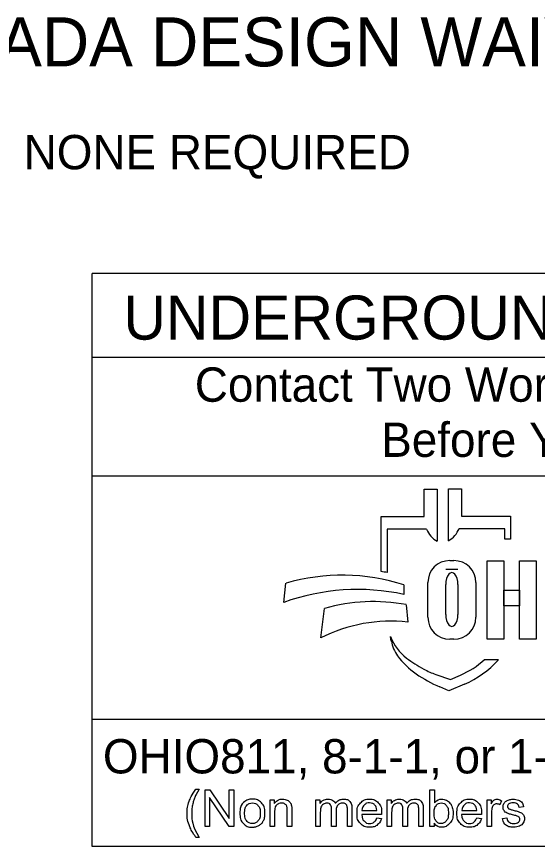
# Model space of a CAD drawing. Extents: x 0 to 34, y 0 to 22.
# Drawn here: x 2.07 to 4.196, y 2.143 to 5.529 of the extents above; entities that cross this region are included whole.
import ezdxf

# ---------------------------------------------------------------- set-up
doc = ezdxf.new("R2010")
doc.units = 0
doc.layers.add('SH_Data', color=7, linetype='Continuous')
doc.layers.add('SH_Text', color=7, linetype='Continuous')

msp = doc.modelspace()

# ---------------------------------------------------------------- linework, layer by layer
at = {"layer": 'SH_Data'}
for p, q in [((2.3775, 2.1428), (2.3775, 4.4803)), ((6.6275, 4.4803), (2.3775, 4.4803)), ((2.3775, 4.1387), (6.6275, 4.1387)), ((2.3775, 3.6553), (6.6275, 3.6553)), ((6.6275, 2.6607), (2.3775, 2.6607)), ((6.6275, 2.1428), (2.3775, 2.1428))]:
    msp.add_line(p, q, dxfattribs=at)
at = {"layer": 'SH_Text'}
for p, q in [((3.7335, 3.4883), (3.7335, 3.5998)), ((3.7335, 3.5998), (3.7872, 3.5998)), ((3.7872, 3.5998), (3.7872, 3.3877)), ((3.8329, 3.39), (3.8329, 3.6021)), ((3.8329, 3.6021), (3.8865, 3.6021)), ((3.8865, 3.6021), (3.8865, 3.4906)), ((3.5576, 3.2644), (3.5576, 3.4883)), ((3.5576, 3.4883), (3.7335, 3.4883)), ((3.8865, 3.4906), (4.0857, 3.4906)), ((4.0857, 3.4906), (4.0857, 3.3968)), ((3.5828, 3.4369), (3.5828, 3.26)), ((3.7439, 3.4369), (3.5828, 3.4369)), ((4.0625, 3.4392), (3.8761, 3.4392)), ((4.0625, 3.3968), (4.0625, 3.4392)), ((4.0857, 3.3968), (4.0625, 3.3968)), ((3.8385, 3.3091), (3.8551, 3.3091)), ((3.8718, 3.2721), (3.822, 3.2721)), ((3.7491, 3.0776), (3.7491, 3.2196)), ((3.9445, 3.2196), (3.9445, 3.0776)), ((3.1602, 3.1381), (3.1696, 3.2162)), ((3.6509, 3.2097), (3.6509, 3.1709)), ((3.822, 3.089), (3.822, 3.2114)), ((3.8718, 3.2114), (3.8718, 3.089)), ((3.6608, 3.1291), (3.6671, 3.0582)), ((3.312, 2.9936), (3.3267, 3.1137)), ((3.5997, 2.9807), (3.5967, 2.9986)), ((3.8551, 2.9882), (3.8385, 2.9882)), ((3.98, 2.9048), (4.0375, 2.9048)), ((3.7816, 2.8444), (3.841, 2.8239)), ((3.841, 2.8239), (3.8821, 2.8417)), ((3.835, 2.7769), (3.7976, 2.7934)), ((3.8983, 2.8044), (3.835, 2.7769))]:
    msp.add_line(p, q, dxfattribs=at)
for points in [[(3.991, 3.3081), (4.0589, 3.3081), (4.0589, 2.9881), (3.991, 2.9881)], [(4.1231, 3.3081), (4.1911, 3.3081), (4.1911, 2.9881), (4.1231, 2.9881)], [(4.0589, 3.1882), (4.1231, 3.1882), (4.1231, 3.1242), (4.0589, 3.1242)]]:
    msp.add_lwpolyline(points, close=True, dxfattribs=at)
for points in [[(2.8021, 2.3766), (2.8153, 2.3766)], [(2.8389, 2.2239), (2.8389, 2.3741), (2.8592, 2.3741), (2.9382, 2.2561), (2.9382, 2.3741), (2.9572, 2.3741), (2.9572, 2.2239), (2.9369, 2.2239), (2.8579, 2.3419), (2.8579, 2.2239), (2.8389, 2.2239)], [(3.7743, 2.2239), (3.7573, 2.2239), (3.7573, 2.3741), (3.7757, 2.3741), (3.7757, 2.3206)], [(3.1048, 2.2239), (3.1048, 2.3328), (3.1214, 2.3328), (3.1214, 2.3173)], [(3.2912, 2.2239), (3.2912, 2.3328), (3.3077, 2.3328), (3.3077, 2.3174)], [(3.5826, 2.2239), (3.5826, 2.3328), (3.5991, 2.3328), (3.5991, 2.3174)], [(3.9904, 2.2239), (3.9904, 2.3328), (4.007, 2.3328), (4.007, 2.3163)], [(4.0495, 2.3293), (4.043, 2.3122)], [(4.1394, 2.3046), (4.1213, 2.3022)], [(3.1233, 2.2833), (3.1233, 2.2239), (3.1048, 2.2239)], [(3.1932, 2.2908), (3.1932, 2.2239), (3.1748, 2.2239), (3.1748, 2.2901)], [(3.3097, 2.2803), (3.3097, 2.2239), (3.2912, 2.2239)], [(3.3743, 2.2871), (3.3743, 2.2239), (3.3559, 2.2239), (3.3559, 2.2946)], [(3.4388, 2.2986), (3.4388, 2.2239), (3.4203, 2.2239), (3.4203, 2.2924)], [(3.56, 2.2736), (3.4788, 2.2736)], [(3.4799, 2.2887), (3.5406, 2.2887)], [(3.601, 2.2803), (3.601, 2.2239), (3.5826, 2.2239)], [(3.6657, 2.2871), (3.6657, 2.2239), (3.6473, 2.2239), (3.6473, 2.2946)], [(3.7301, 2.2986), (3.7301, 2.2239), (3.7117, 2.2239), (3.7117, 2.2924)], [(3.968, 2.2736), (3.8868, 2.2736)], [(3.8879, 2.2887), (3.9486, 2.2887)], [(4.0088, 2.2809), (4.0088, 2.2239), (3.9904, 2.2239)], [(3.5404, 2.2591), (3.5595, 2.2567)], [(3.7743, 2.2375), (3.7743, 2.2239)], [(3.9484, 2.2591), (3.9675, 2.2567)], [(4.053, 2.2564), (4.0712, 2.2593)], [(2.8153, 2.1798), (2.8021, 2.1798)]]:
    msp.add_lwpolyline(points, dxfattribs=at)
for centre, radius, start, end in [((3.8353, 3.4736), 0.0985, 201.9296, 240.7469), ((3.7847, 3.476), 0.0985, 299.2531, 338.0704), ((3.8385, 3.2196), 0.0895, 90, 180), ((3.8551, 3.2196), 0.0895, 0, 90), ((3.4295, 2.4554), 0.8191, 79.2074, 81.0007), ((3.3997, 2.4302), 0.8191, 72.1402, 106.3144), ((3.4628, 2.2991), 0.8919, 77.8238, 109.8274), ((3.5267, 2.4094), 0.7322, 79.44, 105.8467), ((3.5987, 2.4262), 0.6357, 83.8248, 116.8021), ((3.8385, 3.0776), 0.0895, 180, 270), ((3.8551, 3.0776), 0.0895, 270, 0), ((3.7841, 3.0707), 0.2008, 201.0457, 232.5314), ((3.741, 3.0048), 0.1433, 189.6817, 216.0884), ((3.8747, 3.1022), 0.3088, 216.0884, 235.7167), ((3.9766, 3.3219), 0.5173, 232.5314, 241.794), ((3.7387, 3.1722), 0.3602, 293.4582, 312.0712), ((3.7387, 3.1722), 0.401, 293.4582, 317.8286), ((4.0412, 3.3465), 0.6044, 235.7167, 246.2325), ((3.8914, 3.1631), 0.3371, 241.794, 250.9821)]:
    msp.add_arc(centre, radius, start, end, dxfattribs=at)
for centre, start_param, end_param in [((3.8469, 3.2114), 4.712389, 7.853982), ((3.8469, 3.089), 1.570796, 4.712389)]:
    msp.add_ellipse(centre, major_axis=(0, 0.0484), ratio=0.514403, start_param=start_param, end_param=end_param, dxfattribs=at)
for points in [[(2.8021, 2.1798), (2.7869, 2.199), (2.7763, 2.2248), (2.7657, 2.2506), (2.7657, 2.2783), (2.7657, 2.3026), (2.7736, 2.325), (2.7829, 2.3509), (2.8021, 2.3766)], [(2.8153, 2.3766), (2.8029, 2.3553), (2.7989, 2.3462), (2.7927, 2.332), (2.7891, 2.3167), (2.7847, 2.2975), (2.7847, 2.2782), (2.7847, 2.2289), (2.8153, 2.1798)], [(2.9814, 2.2783), (2.9814, 2.3085), (2.9981, 2.3231), (3.0122, 2.3352), (3.0323, 2.3352), (3.0547, 2.3352), (3.069, 2.3205), (3.0832, 2.3058), (3.0832, 2.2799), (3.0832, 2.2589), (3.0769, 2.2469), (3.0706, 2.2348), (3.0586, 2.2282), (3.0466, 2.2215), (3.0323, 2.2215), (3.0095, 2.2215), (2.9954, 2.2362), (2.9814, 2.2508), (2.9814, 2.2783)], [(3.0003, 2.2783), (3.0003, 2.2574), (3.0094, 2.247), (3.0185, 2.2366), (3.0323, 2.2366), (3.046, 2.2366), (3.0551, 2.2471), (3.0642, 2.2575), (3.0642, 2.279), (3.0642, 2.2991), (3.0551, 2.3095), (3.0459, 2.3199), (3.0323, 2.3199), (3.0185, 2.3199), (3.0094, 2.3096), (3.0003, 2.2992), (3.0003, 2.2783)], [(3.1214, 2.3173), (3.1334, 2.3352), (3.156, 2.3352), (3.1659, 2.3352), (3.1741, 2.3316), (3.1823, 2.3281), (3.1864, 2.3224), (3.1905, 2.3166), (3.1922, 2.3087), (3.1932, 2.3036), (3.1932, 2.2908)], [(3.1748, 2.2901), (3.1748, 2.3013), (3.1726, 2.3069), (3.1705, 2.3125), (3.165, 2.3158), (3.1595, 2.3191), (3.1521, 2.3191), (3.1404, 2.3191), (3.1318, 2.3117), (3.1233, 2.3042), (3.1233, 2.2833)], [(3.3077, 2.3174), (3.3128, 2.3254), (3.3214, 2.3303), (3.3299, 2.3352), (3.3407, 2.3352), (3.3528, 2.3352), (3.3606, 2.3301), (3.3683, 2.3251), (3.3715, 2.3161), (3.3844, 2.3352), (3.4051, 2.3352), (3.4213, 2.3352), (3.43, 2.3262), (3.4388, 2.3172), (3.4388, 2.2986)], [(3.3559, 2.2946), (3.3559, 2.3069), (3.3514, 2.313), (3.3469, 2.3191), (3.3366, 2.3191), (3.3288, 2.3191), (3.3222, 2.315), (3.3156, 2.311), (3.3126, 2.3031), (3.3097, 2.2952), (3.3097, 2.2803)], [(3.4203, 2.2924), (3.4203, 2.3035), (3.4185, 2.3083), (3.4168, 2.3132), (3.412, 2.3162), (3.4073, 2.3191), (3.401, 2.3191), (3.3895, 2.3191), (3.3819, 2.3115), (3.3743, 2.3039), (3.3743, 2.2871)], [(3.5595, 2.2567), (3.555, 2.24), (3.5428, 2.2307), (3.5306, 2.2215), (3.5117, 2.2215), (3.4878, 2.2215), (3.4738, 2.2362), (3.4598, 2.2509), (3.4598, 2.2774), (3.4598, 2.3049), (3.474, 2.32), (3.4881, 2.3352), (3.5106, 2.3352), (3.5324, 2.3352), (3.5463, 2.3203), (3.5601, 2.3055), (3.5601, 2.2785), (3.5601, 2.2769), (3.56, 2.2736)], [(3.5406, 2.2887), (3.5394, 2.3025), (3.5337, 2.3094), (3.5249, 2.3201), (3.5108, 2.3201), (3.4981, 2.3201), (3.4894, 2.3115), (3.4808, 2.303), (3.4799, 2.2887)], [(3.5991, 2.3174), (3.6042, 2.3254), (3.6127, 2.3303), (3.6212, 2.3352), (3.6321, 2.3352), (3.6442, 2.3352), (3.6519, 2.3301), (3.6597, 2.3251), (3.6628, 2.3161), (3.6758, 2.3352), (3.6965, 2.3352), (3.7127, 2.3352), (3.7214, 2.3262), (3.7301, 2.3172), (3.7301, 2.2986)], [(3.6473, 2.2946), (3.6473, 2.3069), (3.6428, 2.313), (3.6383, 2.3191), (3.628, 2.3191), (3.6202, 2.3191), (3.6136, 2.315), (3.607, 2.311), (3.604, 2.3031), (3.601, 2.2952), (3.601, 2.2803)], [(3.7117, 2.2924), (3.7117, 2.3035), (3.7099, 2.3083), (3.7081, 2.3132), (3.7034, 2.3162), (3.6987, 2.3191), (3.6923, 2.3191), (3.6809, 2.3191), (3.6733, 2.3115), (3.6657, 2.3039), (3.6657, 2.2871)], [(3.7741, 2.2792), (3.7741, 2.2596), (3.7794, 2.2509), (3.7881, 2.2366), (3.8029, 2.2366), (3.815, 2.2366), (3.8238, 2.2471), (3.8326, 2.2576), (3.8326, 2.2784), (3.8326, 2.2998), (3.8241, 2.3099), (3.8157, 2.3201), (3.8038, 2.3201), (3.7917, 2.3201), (3.7829, 2.3096), (3.7741, 2.299), (3.7741, 2.2792)], [(3.7757, 2.3206), (3.7874, 2.3352), (3.8055, 2.3352), (3.8155, 2.3352), (3.8245, 2.3311), (3.8335, 2.3271), (3.8392, 2.3198), (3.845, 2.3124), (3.8483, 2.3021), (3.8516, 2.2918), (3.8516, 2.28), (3.8516, 2.252), (3.8378, 2.2368), (3.8239, 2.2215), (3.8046, 2.2215), (3.7853, 2.2215), (3.7743, 2.2375)], [(3.9675, 2.2567), (3.963, 2.24), (3.9508, 2.2307), (3.9386, 2.2215), (3.9196, 2.2215), (3.8958, 2.2215), (3.8818, 2.2362), (3.8678, 2.2509), (3.8678, 2.2774), (3.8678, 2.3049), (3.882, 2.32), (3.8961, 2.3352), (3.9186, 2.3352), (3.9404, 2.3352), (3.9543, 2.3203), (3.9681, 2.3055), (3.9681, 2.2785), (3.9681, 2.2769), (3.968, 2.2736)], [(3.9486, 2.2887), (3.9474, 2.3025), (3.9417, 2.3094), (3.9328, 2.3201), (3.9188, 2.3201), (3.9061, 2.3201), (3.8974, 2.3115), (3.8888, 2.303), (3.8879, 2.2887)], [(4.007, 2.3163), (4.0133, 2.3278), (4.0187, 2.3315), (4.0241, 2.3352), (4.0305, 2.3352), (4.0398, 2.3352), (4.0495, 2.3293)], [(4.043, 2.3122), (4.0363, 2.3162), (4.0295, 2.3162), (4.0235, 2.3162), (4.0187, 2.3125), (4.0139, 2.3089), (4.0119, 2.3024), (4.0088, 2.2926), (4.0088, 2.2809)], [(4.1213, 2.3022), (4.1201, 2.3106), (4.1142, 2.3153), (4.1083, 2.3201), (4.0975, 2.3201), (4.0848, 2.3201), (4.0794, 2.3159), (4.0739, 2.3116), (4.0739, 2.306), (4.0739, 2.3024), (4.0762, 2.2995), (4.0785, 2.2966), (4.0833, 2.2946), (4.086, 2.2936), (4.0996, 2.2899), (4.1192, 2.2847), (4.1269, 2.2813), (4.1347, 2.278), (4.1391, 2.2717), (4.1435, 2.2653), (4.1435, 2.2559), (4.1435, 2.2467), (4.1381, 2.2386), (4.1327, 2.2304), (4.1226, 2.226), (4.1124, 2.2215), (4.0996, 2.2215), (4.0784, 2.2215), (4.0672, 2.2303), (4.0561, 2.2391), (4.053, 2.2564)], [(4.0712, 2.2593), (4.0727, 2.2483), (4.0798, 2.2425), (4.0868, 2.2366), (4.0995, 2.2366), (4.1122, 2.2366), (4.1184, 2.2418), (4.1245, 2.247), (4.1245, 2.254), (4.1245, 2.2602), (4.1191, 2.2638), (4.1153, 2.2663), (4.1002, 2.2701), (4.0799, 2.2752), (4.072, 2.2789), (4.0642, 2.2827), (4.0601, 2.2893), (4.0561, 2.2959), (4.0561, 2.3038), (4.0561, 2.3111), (4.0594, 2.3173), (4.0628, 2.3235), (4.0685, 2.3276), (4.0728, 2.3308), (4.0803, 2.333), (4.0877, 2.3352), (4.0962, 2.3352), (4.109, 2.3352), (4.1187, 2.3315), (4.1284, 2.3278), (4.133, 2.3215), (4.1377, 2.3152), (4.1394, 2.3046)], [(3.4788, 2.2736), (3.4799, 2.2557), (3.489, 2.2462), (3.4981, 2.2366), (3.5117, 2.2366), (3.5219, 2.2366), (3.5291, 2.242), (3.5362, 2.2473), (3.5404, 2.2591)], [(3.8868, 2.2736), (3.8879, 2.2557), (3.897, 2.2462), (3.9061, 2.2366), (3.9197, 2.2366), (3.9299, 2.2366), (3.937, 2.242), (3.9442, 2.2473), (3.9484, 2.2591)]]:
    msp.add_open_spline(points, degree=3, dxfattribs=at)

# ---------------------------------------------------------------- texts
for s, height, p in [('ADA DESIGN WAIVERS', 0.2, (1.9944, 5.3256)), ('  NONE REQUIRED                          ', 0.14, (1.9944, 4.9056)), ('UNDERGROUND UTILITIES', 0.18, (2.5057, 4.2106)), ('Contact Two Working Days', 0.14, (2.7972, 3.9571)), ('Before You Dig', 0.14, (3.5583, 3.7321)), ('OHIO811, 8-1-1, or 1-800-362-2764', 0.14, (2.422, 2.4406))]:
    msp.add_text(s, height=height, dxfattribs=at).set_placement(p)

doc.saveas('drawing.dxf')
